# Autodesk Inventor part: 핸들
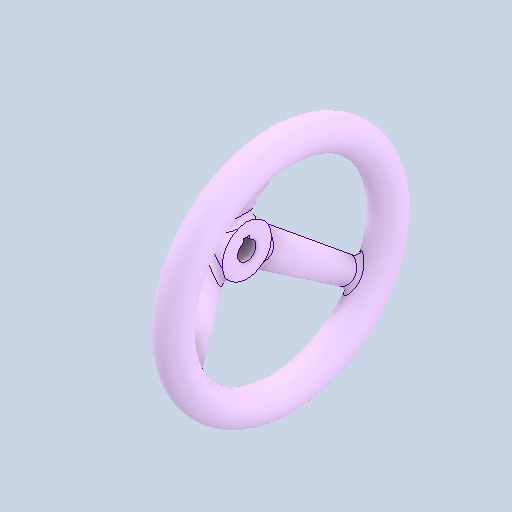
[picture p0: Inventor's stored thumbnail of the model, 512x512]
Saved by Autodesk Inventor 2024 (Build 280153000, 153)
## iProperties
Created: 2024-07
Part Number: 핸들
Material: 강철, 연강
Document SubType Name: Modeling
Designer: com
Density: 7.85 g/cm^3
Appearance: 기본값
Author: jhkim
Sending System: Autodesk Inventor 2025
Preprocessor: ST-DEVELOPER v20
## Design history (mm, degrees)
feature "솔리드1"
node "솔리드2"
